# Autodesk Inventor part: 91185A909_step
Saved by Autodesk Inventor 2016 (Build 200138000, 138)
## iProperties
Created: 2016-03
Part Number: 91185A909_step
Material: Generic
Document SubType Name: Modeling
Designer: bongo_000
Density: 1 g/cm^3
Appearance: Default
Author: bongo_000
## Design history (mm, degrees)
feature "SOLID1"
body "Solid1"
